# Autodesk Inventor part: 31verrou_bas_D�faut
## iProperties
Created: 2011-01
Part Number: 31verrou_bas_D�faut
Document SubType Name: Modeling
Designer: eric
Density: 1 g/cm^3
Mass: 14.4766 g
Surface Area: 112.976 cm^2
Volume: 14.4766 cm^3
Author: eric
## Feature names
1. Base1
